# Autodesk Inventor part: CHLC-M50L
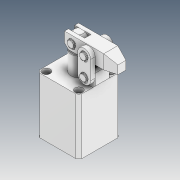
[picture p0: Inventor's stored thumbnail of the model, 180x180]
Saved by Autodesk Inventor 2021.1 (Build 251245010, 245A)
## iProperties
Created: 2019-11
Part Number: CHLC-M50L
Material: Ogólny
Description: STEP AP214
Document SubType Name: Modeling
Designer: user
Density: 1 g/cm^3
Appearance: Domyślna
Company: Microsoft
Title: chlc-m50_asm-L.STEP
Author: Windows
Revision Number: ÈÎºÎ
Sending System: SolidWorks 2015
Preprocessor: SwSTEP 2.0
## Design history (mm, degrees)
feature "CHLC-50-01-1-solid1"
feature "M6LS_1-2-solid1"
feature "chlc-m50_asm-±¾Ìå×é¼þ-L-1_CHLC-50£­Í¹Ì¨-1-solid1"
feature "CHLC-50-04-2-solid1"
feature "CHLC-50-02-1-solid1"
feature "CHLC-50-06-6-solid1"
feature "CHLC-50-09-1-solid1"
feature "M6LS_1-1-solid1"
feature "CHLC-50-06-5-solid1"
feature "CHLC-50-06-4-solid1"
feature "CHLC-50-06-1-solid1"
feature "CHLC-50-03-2-solid1"
feature "CHLC-50-06-2-solid1"
feature "CHLC-50-04-1-solid1"
feature "CHLC-50-03-1-solid1"
feature "CHLC-50-06-3-solid1"
feature "Í¹Ì¨-À­Éì1"
node "Bryła1"
node "Bryła2"
node "Bryła3"
node "Bryła4"
node "Bryła5"
node "Bryła6"
node "Bryła7"
node "Bryła8"
node "Bryła9"
node "Bryła10"
node "Bryła11"
node "Bryła12"
node "Bryła13"
node "Bryła14"
node "Bryła15"
node "Bryła16"
node "Bryła17"
